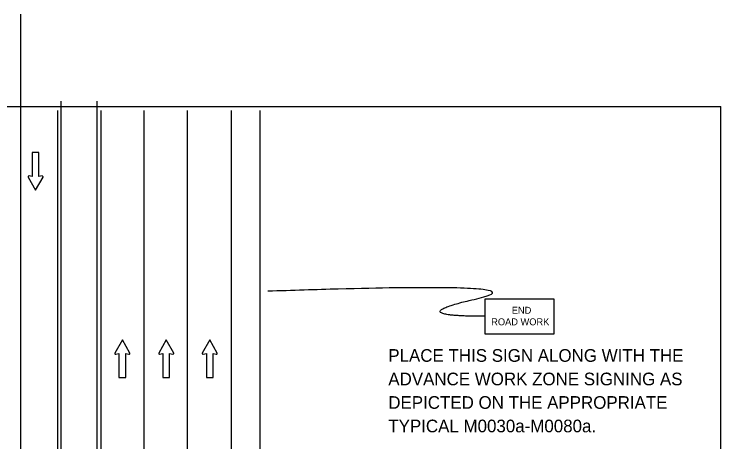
# Model space of a CAD drawing. Extents: x 16723 to 18475, y 7015 to 8267.
# Drawn here: x 17031.7 to 17422.8, y 8030.8 to 8267.4 of the extents above; entities that cross this region are included whole.
import ezdxf

# ---------------------------------------------------------------- set-up
doc = ezdxf.new("R2010")
doc.units = 0
for name, color, linetype in [('ALI_LEGAL_EX', 7, 'Continuous'), ('BORDER', 7, 'Continuous'), ('MT_SCRATCH_LEVEL_E', 7, 'Continuous'), ('PAVT_EDGE_EX', 7, 'Continuous'), ('TRAFFIC_SIGNS_PR', 7, 'Continuous')]:
    doc.layers.add(name, color=color, linetype=linetype)

msp = doc.modelspace()

# ---------------------------------------------------------------- linework, layer by layer
at = {"layer": 'ALI_LEGAL_EX'}
for p, q in [((17057.71, 7347.02), (17057.71, 8219.23)), ((17077.71, 7347.02), (17077.71, 8219.23)), ((17103.71, 7341.97), (17103.71, 8214.17)), ((17127.71, 7341.97), (17127.71, 8214.17))]:
    msp.add_line(p, q, dxfattribs=at)
for points in [[(17057.71, 8141.97), (17057.71, 8166.97)], [(17077.71, 8141.97), (17077.71, 8166.97)], [(17103.71, 8141.97), (17103.71, 8166.97)], [(17127.71, 8141.97), (17127.71, 8166.97)], [(17057.71, 8041.97), (17057.71, 8066.97)], [(17077.71, 8041.97), (17077.71, 8066.97)], [(17103.71, 8041.97), (17103.71, 8066.97)], [(17127.71, 8041.97), (17127.71, 8066.97)]]:
    msp.add_lwpolyline(points, dxfattribs=at)
at = {"layer": 'BORDER'}
for p in [(16722.75, 8216.25), (17422.75, 7216.25)]:
    msp.add_line(p, (17422.75, 8216.25), dxfattribs=at)
at = {"layer": 'MT_SCRATCH_LEVEL_E'}
for p, q in [((17045.45, 8190.82), (17041.71, 8190.82)), ((17041.71, 8190.82), (17041.71, 8177.56)), ((17045.45, 8190.82), (17041.71, 8190.82)), ((17041.71, 8190.82), (17041.71, 8177.56)), ((17045.45, 8190.82), (17041.71, 8190.82)), ((17041.71, 8190.82), (17041.71, 8177.56)), ((17045.45, 8190.82), (17041.71, 8190.82)), ((17041.71, 8190.82), (17041.71, 8177.56)), ((17045.45, 8177.56), (17045.45, 8190.82)), ((17045.45, 8177.56), (17045.45, 8190.82)), ((17045.45, 8177.56), (17045.45, 8190.82)), ((17045.45, 8177.56), (17045.45, 8190.82)), ((17039.45, 8177.19), (17043.6, 8169.95)), ((17039.45, 8177.19), (17043.6, 8169.95)), ((17039.45, 8177.19), (17043.6, 8169.95)), ((17039.45, 8177.19), (17043.6, 8169.95)), ((17041.71, 8177.56), (17039.93, 8177.88)), ((17041.71, 8177.56), (17039.93, 8177.88)), ((17041.71, 8177.56), (17039.93, 8177.88)), ((17041.71, 8177.56), (17039.93, 8177.88)), ((17043.6, 8169.95), (17047.71, 8177.19)), ((17043.6, 8169.95), (17047.71, 8177.19)), ((17043.6, 8169.95), (17047.71, 8177.19)), ((17043.6, 8169.95), (17047.71, 8177.19)), ((17047.23, 8177.88), (17045.45, 8177.56)), ((17047.23, 8177.88), (17045.45, 8177.56)), ((17047.23, 8177.88), (17045.45, 8177.56)), ((17047.23, 8177.88), (17045.45, 8177.56)), ((17091.58, 8087.21), (17087.47, 8079.97)), ((17091.58, 8087.21), (17087.47, 8079.97)), ((17095.73, 8079.97), (17091.58, 8087.21)), ((17095.73, 8079.97), (17091.58, 8087.21)), ((17115.85, 8087.21), (17111.74, 8079.97)), ((17115.85, 8087.21), (17111.74, 8079.97)), ((17120, 8079.97), (17115.85, 8087.21)), ((17120, 8079.97), (17115.85, 8087.21)), ((17139.92, 8087.21), (17135.81, 8079.97)), ((17139.92, 8087.21), (17135.81, 8079.97)), ((17144.07, 8079.97), (17139.92, 8087.21)), ((17144.07, 8079.97), (17139.92, 8087.21)), ((17087.95, 8079.29), (17089.73, 8079.61)), ((17087.95, 8079.29), (17089.73, 8079.61)), ((17089.73, 8079.61), (17089.73, 8066.35)), ((17089.73, 8079.61), (17089.73, 8066.35)), ((17093.47, 8066.35), (17093.47, 8079.61)), ((17093.47, 8079.61), (17095.25, 8079.29)), ((17093.47, 8066.35), (17093.47, 8079.61)), ((17093.47, 8079.61), (17095.25, 8079.29)), ((17112.22, 8079.29), (17114, 8079.61)), ((17112.22, 8079.29), (17114, 8079.61)), ((17114, 8079.61), (17114, 8066.35)), ((17114, 8079.61), (17114, 8066.35)), ((17117.74, 8066.35), (17117.74, 8079.61)), ((17117.74, 8079.61), (17119.52, 8079.29)), ((17117.74, 8066.35), (17117.74, 8079.61)), ((17117.74, 8079.61), (17119.52, 8079.29)), ((17136.29, 8079.29), (17138.07, 8079.61)), ((17136.29, 8079.29), (17138.07, 8079.61)), ((17138.07, 8079.61), (17138.07, 8066.35)), ((17138.07, 8079.61), (17138.07, 8066.35)), ((17141.81, 8066.35), (17141.81, 8079.61)), ((17141.81, 8079.61), (17143.59, 8079.29)), ((17141.81, 8066.35), (17141.81, 8079.61)), ((17141.81, 8079.61), (17143.59, 8079.29)), ((17089.73, 8066.35), (17093.47, 8066.35)), ((17089.73, 8066.35), (17093.47, 8066.35)), ((17114, 8066.35), (17117.74, 8066.35)), ((17114, 8066.35), (17117.74, 8066.35)), ((17138.07, 8066.35), (17141.81, 8066.35)), ((17138.07, 8066.35), (17141.81, 8066.35))]:
    msp.add_line(p, q, dxfattribs=at)
for centre, start, end in [((17039.86, 8177.42), 80.0362, 209.7731), ((17039.86, 8177.42), 80.0362, 209.7731), ((17039.86, 8177.42), 80.0362, 209.7731), ((17039.86, 8177.42), 80.0362, 209.7731), ((17047.3, 8177.42), 330.4248, 99.9638), ((17047.3, 8177.42), 330.4248, 99.9638), ((17047.3, 8177.42), 330.4248, 99.9638), ((17047.3, 8177.42), 330.4248, 99.9638), ((17087.88, 8079.75), 150.4248, 279.9638), ((17087.88, 8079.75), 150.4248, 279.9638), ((17095.32, 8079.75), 260.0362, 29.7731), ((17095.32, 8079.75), 260.0362, 29.7731), ((17112.15, 8079.75), 150.4248, 279.9638), ((17112.15, 8079.75), 150.4248, 279.9638), ((17119.59, 8079.75), 260.0362, 29.7731), ((17119.59, 8079.75), 260.0362, 29.7731), ((17136.22, 8079.75), 150.4248, 279.9638), ((17136.22, 8079.75), 150.4248, 279.9638), ((17143.66, 8079.75), 260.0362, 29.7731), ((17143.66, 8079.75), 260.0362, 29.7731)]:
    msp.add_arc(centre, 0.463, start, end, dxfattribs=at)
at = {"layer": 'PAVT_EDGE_EX'}
for p, q in [((17035.15, 8267.39), (17035.15, 7438.21)), ((17055.71, 8214.17), (17055.71, 7956.5)), ((17079.71, 8214.17), (17079.71, 7981.61)), ((17151.71, 8214.17), (17151.71, 7352.81)), ((17167.71, 8214.17), (17167.71, 7352.81))]:
    msp.add_line(p, q, dxfattribs=at)
at = {"layer": 'TRAFFIC_SIGNS_PR'}
msp.add_lwpolyline([(17292.07, 8090.55), (17330.47, 8090.55), (17330.47, 8109.75), (17292.07, 8109.75)], close=True, dxfattribs=at)
msp.add_open_spline([(17292.23, 8100.27), (17244.99, 8100.27), (17330.01, 8119.62), (17172.05, 8114.12)], degree=2, dxfattribs=at)

# ---------------------------------------------------------------- texts
for s, height, p in [('END', 3.831, (17307.07, 8101.68)), ('ROAD WORK', 3.831, (17295.68, 8095.3)), ('PLACE THIS SIGN ALONG WITH THE', 7, (17238.74, 8075.11)), ('ADVANCE WORK ZONE SIGNING AS', 7, (17238.74, 8062.11)), ('DEPICTED ON THE APPROPRIATE', 7, (17238.74, 8049.11)), ('TYPICAL M0030a-M0080a.', 7, (17238.74, 8036.11))]:
    msp.add_text(s, height=height, dxfattribs=at).set_placement(p)

doc.saveas('drawing.dxf')
